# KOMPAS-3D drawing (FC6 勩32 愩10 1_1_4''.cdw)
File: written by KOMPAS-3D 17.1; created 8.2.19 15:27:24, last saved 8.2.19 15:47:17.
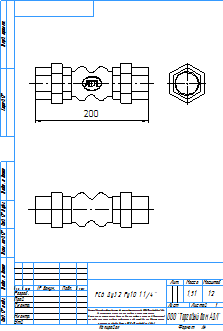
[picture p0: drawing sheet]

Sheet 1: A4, portrait

Title block, sheet 1: name: FC6 Ду32 Ру10 1 1/4''; mass: 1,51; sheets: 1; sheet format: A4; stored path: \\adlc.lan\data\АДЛ_ПКД\3D-модели\ADL production\Гибкие вставки серии FC\FC6\KOMPAS 2D\FC6 Ду32 Ру10 1_1_4''.cdw

Views: Вид 1
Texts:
  kka
  adl
  Рама для чертежей
  Лит-Масса-Масштаб
  Материал-Предприятие
  Масштаб
  Изм.
  Лист
  № докум.
  Подп.
  Дата
  Лит.
  Разраб.
  Пров.
  Т.контр.
  Листов
  Внимание! Данный продукт является объектом авторского права ООО «Торговый Дом АДЛ».
  Запрещается изменение, копирование, распространение
  (в том числе путем копирования на другие сайты и ресурсы в Интернете)
  или любое иное использование информации и объектов без предварительного
  согласия правообладателя (ООО «Торговый Дом АДЛ»).
  Н.контр.
  Утв.
  ООО "Торговый дом АДЛ"
  Изменение
  Номер документа
  Подпись
  Обозначение документа
  Наименование изделия
  Масса изделия по ГОСТ 2.109-73
  Порядковый номер листа
  Общее количество листов в документе
  Характер работы, выполненной лицом, подписавшим документ
  Наименование или индекс предприятия, выпускающего документ
  Инв. № подл.
  Подп. и дата
  Взам. инв. №
  Инв. № дубл.
  Инвентарный номер подлинника по ГОСТ 2.501-68
  Подпись принявшего подлинник в отдел технической документации
  Инвентарный номер подлинника, взамен которого выпущен данный подлинник
  Инвентарный номер дубликата по ГОСТ 2.502-68
  Подпись принявшего дубликат в отдел технической документации
  Справ. №
  Перв. примен.
  Обозначение документа, взамен или на основании которого выпущен данный документ
  Обозначение документа, в котором впервые записан данный документ
  Подпись лица, копировавшего чертеж
  Обозначение формата листа
  !Рама для чертежа
Dimensions and other numbers on the sheet: 200; 1:2; 1; 1,51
